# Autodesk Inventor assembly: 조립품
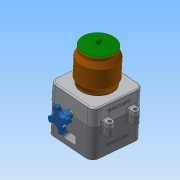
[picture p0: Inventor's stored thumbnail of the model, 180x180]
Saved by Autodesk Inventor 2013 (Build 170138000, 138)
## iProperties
Created: 2018-01
Part Number: 조립품
Document SubType Name: Assembly
Designer: Administrator
Author: Administrator
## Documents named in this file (9)
- C:\Users\Administrator\Desktop\480108V1031\조립품.iam
- C:\Users\Administrator\Desktop\480108V1031\본체.ipt
- C:\Users\Administrator\Desktop\480108V1031\핸들축.ipt
- C:\Users\Administrator\Desktop\480108V1031\핸들.ipt
- C:\Users\Administrator\Desktop\480108V1031\볼트 M3x12.ipt
- C:\Users\Administrator\Desktop\480108V1031\본체커버.ipt
- C:\Users\Administrator\Desktop\480108V1031\용기.ipt
- C:\Users\Administrator\Desktop\480108V1031\용기캡.ipt
- C:\Users\Administrator\Desktop\480108V1031\볼트 M4x12.ipt
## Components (2 placed, 2 different names)
1. 핸들축:1
2. 핸들:1
